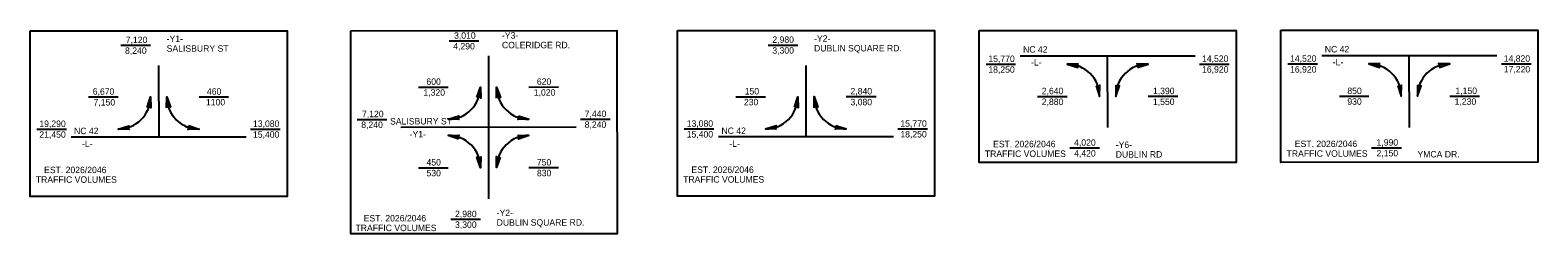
# Model space of a CAD drawing. Extents: x 962371 to 964823, y 1145061 to 1145393.
import ezdxf

# ---------------------------------------------------------------- set-up
doc = ezdxf.new("R2010")
doc.units = 0
doc.layers.add('Prop DSN Text', color=7, linetype='Continuous')
doc.layers.add('Prop PHM Traffic Signal CELL', color=7, linetype='Continuous')

msp = doc.modelspace()

# ---------------------------------------------------------------- linework, layer by layer
at = {"layer": 'Prop DSN Text'}
for p, q in [((962518.7, 1145368.4), (962567, 1145368.4)), ((963052.6, 1145375.6), (963100.8, 1145375.6)), ((963571.6, 1145368.7), (963619.8, 1145368.7)), ((962466.2, 1145284.4), (962514.5, 1145284.4)), ((962645.8, 1145284.4), (962694, 1145284.4)), ((963002.8, 1145300.3), (963051, 1145300.4)), ((963182.3, 1145300.4), (963230.5, 1145300.5)), ((963519.1, 1145284.7), (963567.3, 1145284.7)), ((963698.6, 1145284.8), (963746.9, 1145284.8)), ((962382.3, 1145231.8), (962430.5, 1145231.9)), ((962729.8, 1145232), (962778, 1145232)), ((962902.9, 1145247.8), (962951.2, 1145247.8)), ((963266.3, 1145248), (963314.6, 1145248)), ((963435.1, 1145232.2), (963483.4, 1145232.2)), ((963782.6, 1145232.3), (963830.9, 1145232.3)), ((963002.8, 1145169.1), (963051.1, 1145169.1)), ((963182.4, 1145169.2), (963230.6, 1145169.2)), ((963055.4, 1145085.1), (963103.7, 1145085.1))]:
    msp.add_line(p, q, dxfattribs=at)
at = {"layer": 'Prop PHM Traffic Signal CELL'}
for p, q in [((962580.1, 1145335.3), (962580.2, 1145218.8)), ((963116.6, 1145351.3), (963116.7, 1145234.8)), ((963633, 1145335.6), (963633, 1145219.1)), ((963925.8, 1145337.7), (963974, 1145337.7)), ((964266, 1145350.9), (963981.3, 1145350.8)), ((964123.7, 1145234.3), (964123.6, 1145350.9)), ((964273.3, 1145337.8), (964321.5, 1145337.8)), ((964416.5, 1145338), (964464.7, 1145338)), ((964756.7, 1145351.2), (964472, 1145351.1)), ((964614.4, 1145234.6), (964614.3, 1145351.2)), ((964764, 1145338.1), (964812.2, 1145338.1)), ((964009.8, 1145285.2), (964058, 1145285.2)), ((964189.3, 1145285.3), (964237.6, 1145285.3)), ((964500.5, 1145285.5), (964548.7, 1145285.5)), ((964680, 1145285.6), (964728.3, 1145285.6)), ((963259, 1145234.9), (962974.3, 1145234.7)), ((963116.7, 1145234.8), (963116.8, 1145118.3)), ((962722.5, 1145218.8), (962437.8, 1145218.7)), ((963775.3, 1145219.2), (963490.6, 1145219.1)), ((964062.3, 1145201.2), (964110.6, 1145201.2)), ((964553, 1145201.5), (964601.3, 1145201.5))]:
    msp.add_line(p, q, dxfattribs=at)
for points in [[(962371.2, 1145392), (962789, 1145392.1), (962789.1, 1145122.4), (962371.3, 1145122.2)], [(962892.7, 1145392.1), (963325.5, 1145392.4), (963325.7, 1145061.7), (962892.9, 1145061.4)], [(963424, 1145392.3), (963841.9, 1145392.4), (963841.9, 1145122.7), (963424.1, 1145122.6)], [(963914.7, 1145392.6), (964332.6, 1145392.7), (964332.6, 1145177.7), (963914.8, 1145177.5)], [(963914.7, 1145392.6), (964332.6, 1145392.7), (964332.6, 1145177.7), (963914.8, 1145177.5)], [(964405.4, 1145392.9), (964823.3, 1145393), (964823.3, 1145178), (964405.5, 1145177.8)], [(964405.4, 1145392.9), (964823.3, 1145393), (964823.3, 1145178), (964405.5, 1145177.8)], [(964076, 1145338.3), (964058, 1145337.7), (964075.2, 1145332.1), (964073.4, 1145335.6)], [(964172.2, 1145332), (964189.3, 1145337.8), (964171.2, 1145338.2), (964173.9, 1145335.4)], [(964566.7, 1145338.6), (964548.7, 1145338), (964565.9, 1145332.4), (964564.1, 1145335.9)], [(964662.9, 1145332.3), (964680, 1145338.1), (964661.9, 1145338.5), (964664.6, 1145335.7)], [(964104.8, 1145302.3), (964110.5, 1145285.2), (964111, 1145303.3), (964108.2, 1145300.6)], [(964136.8, 1145303.2), (964136.8, 1145285.2), (964142.9, 1145302.3), (964139.4, 1145300.6)], [(964595.5, 1145302.6), (964601.2, 1145285.5), (964601.7, 1145303.6), (964598.9, 1145300.9)], [(964627.5, 1145303.5), (964627.5, 1145285.5), (964633.6, 1145302.6), (964630.1, 1145300.9)], [(962561.3, 1145267.3), (962567, 1145284.4), (962567.4, 1145266.3), (962564.7, 1145269)], [(962593.2, 1145266.4), (962593.3, 1145284.4), (962599.4, 1145267.4), (962595.9, 1145269.1)], [(963097.8, 1145283.3), (963103.5, 1145300.4), (963104, 1145282.3), (963101.2, 1145285)], [(963129.8, 1145282.4), (963129.8, 1145300.4), (963135.9, 1145283.4), (963132.4, 1145285.1)], [(963614.2, 1145267.7), (963619.8, 1145284.7), (963620.3, 1145266.7), (963617.5, 1145269.4)], [(963646.1, 1145266.8), (963646.1, 1145284.8), (963652.2, 1145267.7), (963648.7, 1145269.4)], [(962532.5, 1145231.3), (962514.5, 1145231.9), (962531.7, 1145237.5), (962529.9, 1145234)], [(962628.7, 1145237.6), (962645.8, 1145231.9), (962627.7, 1145231.5), (962630.4, 1145234.3)], [(963069, 1145247.3), (963051.1, 1145247.9), (963068.3, 1145253.4), (963066.5, 1145250)], [(963165.2, 1145253.6), (963182.3, 1145247.9), (963164.2, 1145247.5), (963166.9, 1145250.3)], [(963585.3, 1145231.6), (963567.4, 1145232.2), (963584.6, 1145237.8), (963582.8, 1145234.4)], [(963681.6, 1145238), (963698.6, 1145232.3), (963680.5, 1145231.9), (963683.2, 1145234.6)], [(963068.1, 1145215.8), (963051.1, 1145221.6), (963069.2, 1145221.9), (963066.4, 1145219.2)], [(963164.3, 1145221.9), (963182.3, 1145221.7), (963165.2, 1145215.8), (963167, 1145219.2)], [(963104, 1145187.1), (963103.6, 1145169.1), (963097.8, 1145186.3), (963101.3, 1145184.5)], [(963135.7, 1145186.2), (963129.9, 1145169.2), (963129.6, 1145187.3), (963132.3, 1145184.5)]]:
    msp.add_lwpolyline(points, close=True, dxfattribs=at)
for centre, start, end in [((964058, 1145285.2), 0.0189, 90.0189), ((964189.3, 1145285.3), 90.0189, 180.0189), ((964548.7, 1145285.5), 0.0189, 90.0189), ((964680, 1145285.6), 90.0189, 180.0189), ((962514.5, 1145284.4), 270.0187, 0.0187), ((962645.8, 1145284.4), 180.0187, 270.0187), ((963051, 1145300.4), 270.0374, 0.0374), ((963182.3, 1145300.4), 180.0374, 270.0374), ((963567.3, 1145284.7), 270.0187, 0.0187), ((963698.6, 1145284.8), 180.0187, 270.0187), ((963051.1, 1145169.1), 0.0374, 90.0374), ((963182.4, 1145169.2), 90.0374, 180.0374)]:
    msp.add_arc(centre, 52.5, start, end, dxfattribs=at)

# ---------------------------------------------------------------- texts
at = {"layer": 'Prop DSN Text'}
for s, rotation, p in [('7,120', 0.0187, (962526.7, 1145371.9)), ('3,010', 0.0374, (963060.6, 1145379.1)), ('2,980', 0.0187, (963578.3, 1145372.3)), ('8,240', 0.0187, (962525.5, 1145354.4)), ('4,290', 0.0374, (963059.3, 1145361.6)), ('3,300', 0.0187, (963578.3, 1145354.7)), ('600', 0.0374, (963015.7, 1145303.9)), ('620', 0.0374, (963195.3, 1145304)), ('6,670', 0.0187, (962473, 1145287.9)), ('7,150', 0.0187, (962474.3, 1145270.3)), ('1100', 0.0187, (962657.1, 1145270.4)), ('460', 0.0187, (962658.7, 1145288)), ('1,320', 0.0374, (963010.8, 1145286.3)), ('1,020', 0.0374, (963190.3, 1145286.4)), ('230', 0.0187, (963532.1, 1145270.7)), ('150', 0.0187, (963533.3, 1145288.2)), ('3,080', 0.0187, (963705.4, 1145270.7)), ('2,840', 0.0187, (963705.4, 1145288.3)), ('7,120', 0.0374, (962910.9, 1145251.3)), ('7,440', 0.0374, (963273.1, 1145251.5)), ('19,290', 0.0187, (962386.1, 1145235.4)), ('13,080', 0.0187, (962733.6, 1145235.5)), ('8,240', 0.0374, (962909.7, 1145233.7)), ('8,240', 0.0374, (963273.1, 1145234)), ('13,080', 0.0187, (963439, 1145235.7)), ('15,770', 0.0187, (963786.5, 1145235.8)), ('21,450', 0.0187, (962386.1, 1145217.8)), ('15,400', 0.0187, (962733.6, 1145217.9)), ('15,400', 0.0187, (963439, 1145218.2)), ('18,250', 0.0187, (963786.5, 1145218.3)), ('450', 0.0374, (963015.8, 1145172.6)), ('750', 0.0374, (963195.3, 1145172.7)), ('EST. 2026/2046', 0.0187, (962393.8, 1145160.2)), ('530', 0.0374, (963015.8, 1145155.1)), ('830', 0.0374, (963195.4, 1145155.2)), ('EST. 2026/2046', 0.0187, (963446.6, 1145160.6)), ('TRAFFIC VOLUMES', 0.0187, (962380.4, 1145144.5)), ('TRAFFIC VOLUMES', 0.0187, (963433.2, 1145144.8)), ('EST. 2026/2046', 0.0374, (962913.7, 1145081.6)), ('2,980', 0.0374, (963062.2, 1145088.6)), ('TRAFFIC VOLUMES', 0.0374, (962900.3, 1145065.8)), ('3,300', 0.0374, (963062.2, 1145071.1))]:
    msp.add_text(s, height=10.5, rotation=rotation, dxfattribs=at).set_placement(p)
at = {"layer": 'Prop PHM Traffic Signal CELL'}
for s, rotation, p in [('-Y1-', 0.0187, (962593.2, 1145373.7)), ('-Y3-', 0.0374, (963138.5, 1145379.2)), ('-Y2-', 0.0187, (963646.1, 1145374)), ('SALISBURY ST', 0.0187, (962593.2, 1145357.9)), ('COLERIDGE RD.', 0.0374, (963138.5, 1145363.5)), ('DUBLIN SQUARE RD.', 0.0187, (963646.1, 1145358.3)), ('15,770', 0.0189, (963929.6, 1145341.2)), ('NC 42', 0.0189, (963986.1, 1145356.4)), ('14,520', 0.0189, (964277.1, 1145341.3)), ('14,520', 0.0189, (964420.3, 1145341.5)), ('NC 42', 0.0189, (964476.8, 1145356.7)), ('14,820', 0.0189, (964767.8, 1145341.6)), ('18,250', 0.0189, (963929.6, 1145323.6)), ('-L-', 0.0189, (963999.1, 1145335.4)), ('16,920', 0.0189, (964277.2, 1145323.8)), ('16,920', 0.0189, (964420.3, 1145323.9)), ('-L-', 0.0189, (964489.8, 1145335.7)), ('17,220', 0.0189, (964767.9, 1145324.1)), ('2,640', 0.0189, (964016.5, 1145288.7)), ('2,880', 0.0189, (964016.5, 1145271.2)), ('1,390', 0.0189, (964197.3, 1145288.8)), ('1,550', 0.0189, (964197.3, 1145271.2)), ('850', 0.0189, (964513.5, 1145289)), ('930', 0.0189, (964513.5, 1145271.5)), ('1,230', 0.0189, (964688, 1145271.5)), ('1,150', 0.0189, (964689.3, 1145289.1)), ('NC 42', 0.0187, (962442.6, 1145223.7)), ('SALISBURY ST', 0.0374, (962956.6, 1145239.4)), ('NC 42', 0.0187, (963495.5, 1145224)), ('-L-', 0.0187, (962455.6, 1145202.7)), ('-Y1-', 0.0374, (962988.4, 1145218.4)), ('-L-', 0.0187, (963508.5, 1145203)), ('EST. 2026/2046', 0.0187, (963937.3, 1145202.4)), ('4,020', 0.0189, (964069.1, 1145204.7)), ('-Y6-', 0.0189, (964136.8, 1145201.2)), ('EST. 2026/2046', 0.0187, (964428, 1145202.7)), ('1,990', 0.0189, (964561, 1145205)), ('TRAFFIC VOLUMES', 0.0187, (963923.9, 1145186.6)), ('4,420', 0.0189, (964069.1, 1145187.2)), ('DUBLIN RD', 0.0189, (964136.8, 1145185.5)), ('TRAFFIC VOLUMES', 0.0187, (964414.6, 1145186.9)), ('2,150', 0.0189, (964561, 1145187.5)), ('YMCA DR.', 0.0189, (964627.5, 1145185.8)), ('-Y2-', 0.0374, (963129.9, 1145090.4)), ('DUBLIN SQUARE RD.', 0.0374, (963129.9, 1145074.7))]:
    msp.add_text(s, height=10.5, rotation=rotation, dxfattribs=at).set_placement(p)

doc.saveas('drawing.dxf')
